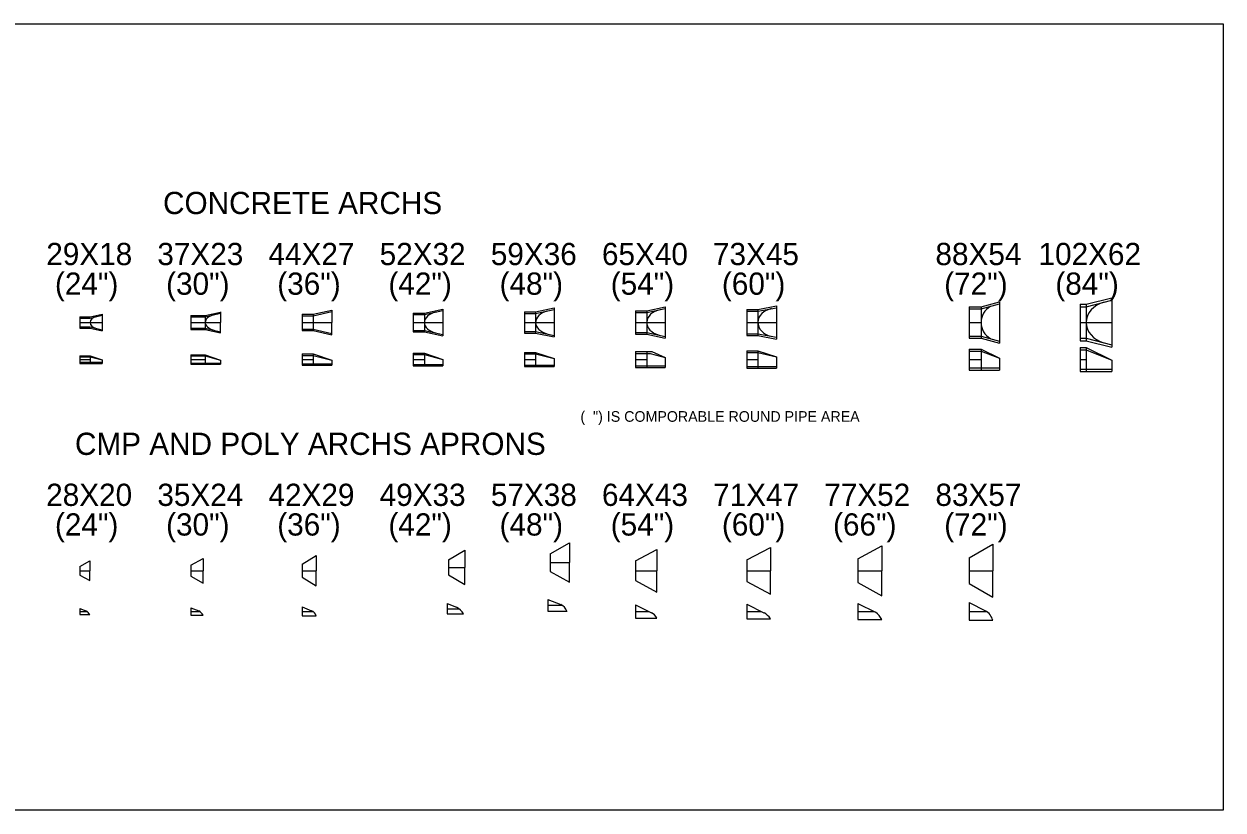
# Model space of a CAD drawing. Extents: x 14089015 to 14094575, y 8545767 to 8546666.
# Drawn here: x 14094251.7 to 14094575.3, y 8546454.2 to 8546666.4 of the extents above; entities that cross this region are included whole.
import ezdxf

# ---------------------------------------------------------------- set-up
doc = ezdxf.new("R2010")
doc.units = 0
doc.layers.add('CulvertExisting', color=7, linetype='Continuous')

msp = doc.modelspace()

# ---------------------------------------------------------------- linework, layer by layer
at = {"layer": 'CulvertExisting'}
for p, q in [((14094538.37, 8546590.73), (14094545.29, 8546592.48)), ((14094538.37, 8546590.06), (14094545.29, 8546591.81)), ((14094545.29, 8546592.48), (14094545.29, 8546579.15)), ((14094300.62, 8546587.69), (14094304.79, 8546588.64)), ((14094300.62, 8546587.36), (14094304.79, 8546588.31)), ((14094304.79, 8546588.65), (14094304.79, 8546585.81)), ((14094329.79, 8546588.02), (14094334.79, 8546589.17)), ((14094329.79, 8546587.65), (14094334.79, 8546588.81)), ((14094334.79, 8546589.17), (14094334.79, 8546585.81)), ((14094356.79, 8546588.36), (14094356.79, 8546583.27)), ((14094356.79, 8546588.36), (14094359.79, 8546588.36)), ((14094359.79, 8546588.36), (14094364.79, 8546589.44)), ((14094359.79, 8546587.98), (14094364.79, 8546589.06)), ((14094359.79, 8546588.36), (14094359.79, 8546583.27)), ((14094364.79, 8546589.44), (14094364.79, 8546582.19)), ((14094386.79, 8546588.69), (14094386.79, 8546582.94)), ((14094386.79, 8546588.69), (14094389.79, 8546588.69)), ((14094386.79, 8546588.27), (14094389.79, 8546588.27)), ((14094389.79, 8546588.69), (14094394.79, 8546589.73)), ((14094389.79, 8546588.27), (14094394.79, 8546589.31)), ((14094389.79, 8546588.69), (14094389.79, 8546582.94)), ((14094394.79, 8546589.73), (14094394.79, 8546581.9)), ((14094416.79, 8546588.98), (14094416.79, 8546582.65)), ((14094416.79, 8546588.98), (14094419.79, 8546588.98)), ((14094416.79, 8546588.52), (14094419.79, 8546588.52)), ((14094419.79, 8546588.98), (14094424.79, 8546590.02)), ((14094419.79, 8546588.52), (14094424.79, 8546589.56)), ((14094419.79, 8546588.98), (14094419.79, 8546582.65)), ((14094424.79, 8546590.02), (14094424.79, 8546581.61)), ((14094446.79, 8546589.36), (14094446.79, 8546582.27)), ((14094446.79, 8546589.36), (14094449.79, 8546589.36)), ((14094446.79, 8546588.86), (14094449.79, 8546588.86)), ((14094449.79, 8546589.36), (14094454.79, 8546590.31)), ((14094449.79, 8546588.86), (14094454.79, 8546589.81)), ((14094449.79, 8546589.36), (14094449.79, 8546582.27)), ((14094454.79, 8546590.31), (14094454.79, 8546581.31)), ((14094506.79, 8546590.06), (14094506.79, 8546581.56)), ((14094506.79, 8546590.06), (14094510.04, 8546590.06)), ((14094506.79, 8546589.48), (14094510.04, 8546589.48)), ((14094510.04, 8546590.06), (14094515.04, 8546591.4)), ((14094510.04, 8546589.48), (14094515.04, 8546590.81)), ((14094510.04, 8546590.06), (14094510.04, 8546581.56)), ((14094515.04, 8546591.4), (14094515.04, 8546580.23)), ((14094536.79, 8546590.73), (14094536.79, 8546580.9)), ((14094536.79, 8546590.73), (14094538.37, 8546590.73)), ((14094536.79, 8546590.06), (14094538.37, 8546590.06)), ((14094538.37, 8546590.73), (14094538.37, 8546580.9)), ((14094266.79, 8546587.31), (14094269.54, 8546587.31)), ((14094266.79, 8546587.31), (14094266.79, 8546584.32)), ((14094266.79, 8546587.02), (14094269.54, 8546587.02)), ((14094266.79, 8546585.81), (14094272.79, 8546585.81)), ((14094269.54, 8546587.31), (14094272.79, 8546588.1)), ((14094269.54, 8546587.02), (14094272.79, 8546587.81)), ((14094272.79, 8546588.1), (14094272.79, 8546583.52)), ((14094296.79, 8546587.69), (14094296.79, 8546583.94)), ((14094296.79, 8546587.69), (14094300.62, 8546587.69)), ((14094296.79, 8546587.36), (14094300.62, 8546587.36)), ((14094296.79, 8546585.81), (14094304.79, 8546585.81)), ((14094300.62, 8546587.69), (14094300.62, 8546583.94)), ((14094304.79, 8546582.98), (14094304.79, 8546585.81)), ((14094326.79, 8546588.02), (14094326.79, 8546583.61)), ((14094326.79, 8546588.02), (14094329.79, 8546588.02)), ((14094326.79, 8546587.65), (14094329.79, 8546587.65)), ((14094326.79, 8546585.81), (14094334.79, 8546585.81)), ((14094329.79, 8546588.02), (14094329.79, 8546583.61)), ((14094334.79, 8546582.46), (14094334.79, 8546585.81)), ((14094356.79, 8546587.98), (14094359.79, 8546587.98)), ((14094356.79, 8546585.81), (14094364.79, 8546585.81)), ((14094386.79, 8546585.81), (14094394.79, 8546585.81)), ((14094416.79, 8546585.81), (14094424.79, 8546585.81)), ((14094446.79, 8546585.81), (14094454.79, 8546585.81)), ((14094506.79, 8546585.81), (14094510.04, 8546585.81)), ((14094536.79, 8546585.81), (14094545.29, 8546585.81)), ((14094266.79, 8546584.61), (14094269.54, 8546584.61)), ((14094266.79, 8546584.32), (14094269.54, 8546584.32)), ((14094269.54, 8546584.61), (14094272.79, 8546583.81)), ((14094269.54, 8546584.32), (14094272.79, 8546583.52)), ((14094296.79, 8546584.27), (14094300.62, 8546584.27)), ((14094296.79, 8546583.94), (14094300.62, 8546583.94)), ((14094300.62, 8546584.27), (14094304.79, 8546583.31)), ((14094300.62, 8546583.94), (14094304.79, 8546582.98)), ((14094326.79, 8546583.98), (14094329.79, 8546583.98)), ((14094326.79, 8546583.61), (14094329.79, 8546583.61)), ((14094329.79, 8546583.98), (14094334.79, 8546582.81)), ((14094329.79, 8546583.61), (14094334.79, 8546582.46)), ((14094356.79, 8546583.65), (14094359.79, 8546583.65)), ((14094356.79, 8546583.27), (14094359.79, 8546583.27)), ((14094359.79, 8546583.65), (14094364.79, 8546582.56)), ((14094359.79, 8546583.27), (14094364.79, 8546582.19)), ((14094386.79, 8546583.36), (14094389.79, 8546583.36)), ((14094386.79, 8546582.94), (14094389.79, 8546582.94)), ((14094389.79, 8546583.36), (14094394.79, 8546582.31)), ((14094389.79, 8546582.94), (14094394.79, 8546581.9)), ((14094416.79, 8546583.11), (14094419.79, 8546583.11)), ((14094416.79, 8546582.65), (14094419.79, 8546582.65)), ((14094419.79, 8546583.11), (14094424.79, 8546582.06)), ((14094419.79, 8546582.65), (14094424.79, 8546581.61)), ((14094446.79, 8546582.77), (14094449.79, 8546582.77)), ((14094446.79, 8546582.27), (14094449.79, 8546582.27)), ((14094449.79, 8546582.77), (14094454.79, 8546581.81)), ((14094449.79, 8546582.27), (14094454.79, 8546581.31)), ((14094506.79, 8546582.15), (14094510.04, 8546582.15)), ((14094510.04, 8546582.15), (14094515.04, 8546580.81)), ((14094506.79, 8546581.56), (14094510.04, 8546581.56)), ((14094506.79, 8546578.65), (14094506.79, 8546572.98)), ((14094506.79, 8546578.65), (14094510.04, 8546578.65)), ((14094510.04, 8546581.56), (14094515.04, 8546580.23)), ((14094510.04, 8546578.65), (14094510.04, 8546572.98)), ((14094510.04, 8546578.65), (14094515.04, 8546576.15)), ((14094536.79, 8546581.56), (14094538.37, 8546581.56)), ((14094536.79, 8546580.9), (14094538.37, 8546580.9)), ((14094536.79, 8546579.06), (14094536.79, 8546572.56)), ((14094536.79, 8546579.06), (14094538.37, 8546579.06)), ((14094538.37, 8546581.56), (14094545.29, 8546579.81)), ((14094538.37, 8546580.9), (14094545.29, 8546579.15)), ((14094538.37, 8546579.06), (14094538.37, 8546572.56)), ((14094538.37, 8546579.06), (14094545.29, 8546575.61)), ((14094266.79, 8546576.85), (14094269.54, 8546576.85)), ((14094266.79, 8546576.85), (14094266.79, 8546574.77)), ((14094266.79, 8546576.56), (14094269.54, 8546576.56)), ((14094266.79, 8546575.81), (14094269.54, 8546575.81)), ((14094269.54, 8546576.85), (14094272.79, 8546575.77)), ((14094269.54, 8546576.85), (14094269.54, 8546574.77)), ((14094269.54, 8546576.56), (14094272.79, 8546575.77)), ((14094272.79, 8546575.77), (14094272.79, 8546574.77)), ((14094296.79, 8546577.1), (14094296.79, 8546574.53)), ((14094296.79, 8546577.1), (14094300.62, 8546577.1)), ((14094296.79, 8546576.77), (14094300.62, 8546576.77)), ((14094296.79, 8546575.81), (14094300.62, 8546575.81)), ((14094300.62, 8546577.1), (14094300.62, 8546574.53)), ((14094300.62, 8546577.1), (14094304.79, 8546575.66)), ((14094300.62, 8546576.77), (14094304.79, 8546575.66)), ((14094304.79, 8546575.66), (14094304.79, 8546574.53)), ((14094326.79, 8546577.31), (14094326.79, 8546574.31)), ((14094326.79, 8546577.31), (14094329.79, 8546577.31)), ((14094326.79, 8546576.94), (14094329.79, 8546576.94)), ((14094326.79, 8546575.81), (14094329.79, 8546575.81)), ((14094329.79, 8546577.31), (14094329.79, 8546574.31)), ((14094329.79, 8546577.31), (14094334.79, 8546575.62)), ((14094329.79, 8546576.94), (14094334.79, 8546575.62)), ((14094334.79, 8546575.62), (14094334.79, 8546574.31)), ((14094356.79, 8546577.52), (14094356.79, 8546574.11)), ((14094356.79, 8546577.52), (14094359.79, 8546577.52)), ((14094356.79, 8546577.15), (14094359.79, 8546577.15)), ((14094356.79, 8546575.81), (14094359.79, 8546575.81)), ((14094359.79, 8546577.52), (14094364.79, 8546575.8)), ((14094359.79, 8546577.15), (14094359.79, 8546574.11)), ((14094359.79, 8546577.15), (14094364.79, 8546575.8)), ((14094364.79, 8546575.8), (14094364.79, 8546574.11)), ((14094386.79, 8546577.73), (14094386.79, 8546573.9)), ((14094386.79, 8546577.73), (14094389.79, 8546577.73)), ((14094386.79, 8546577.31), (14094389.79, 8546577.31)), ((14094386.79, 8546575.81), (14094389.79, 8546575.81)), ((14094389.79, 8546577.73), (14094389.79, 8546573.9)), ((14094389.79, 8546577.73), (14094394.79, 8546576.06)), ((14094389.79, 8546577.31), (14094394.79, 8546576.06)), ((14094394.79, 8546576.06), (14094394.79, 8546573.9)), ((14094416.79, 8546577.94), (14094416.79, 8546573.69)), ((14094416.79, 8546577.94), (14094421.13, 8546577.94)), ((14094416.79, 8546577.48), (14094420.72, 8546577.48)), ((14094416.79, 8546575.81), (14094419.79, 8546575.81)), ((14094419.79, 8546577.94), (14094419.79, 8546573.69)), ((14094420.72, 8546577.48), (14094424.79, 8546576.36)), ((14094421.21, 8546577.94), (14094424.79, 8546576.36)), ((14094424.79, 8546576.36), (14094424.79, 8546573.69)), ((14094446.79, 8546578.19), (14094446.79, 8546573.44)), ((14094446.79, 8546578.19), (14094449.79, 8546578.19)), ((14094446.79, 8546577.69), (14094449.79, 8546577.69)), ((14094446.79, 8546575.81), (14094449.79, 8546575.81)), ((14094449.79, 8546578.19), (14094449.79, 8546573.44)), ((14094449.79, 8546578.19), (14094454.79, 8546576.52)), ((14094449.79, 8546577.69), (14094454.79, 8546576.52)), ((14094454.79, 8546576.52), (14094454.79, 8546573.44)), ((14094506.79, 8546578.06), (14094510.04, 8546578.06)), ((14094506.79, 8546575.81), (14094510.04, 8546575.81)), ((14094510.04, 8546578.06), (14094515.04, 8546576.15)), ((14094515.04, 8546576.15), (14094515.04, 8546572.98)), ((14094536.79, 8546578.4), (14094538.37, 8546578.4)), ((14094536.79, 8546575.81), (14094538.37, 8546575.81)), ((14094538.37, 8546578.4), (14094545.29, 8546575.61)), ((14094545.29, 8546575.61), (14094545.29, 8546572.56)), ((14094266.79, 8546575.06), (14094272.79, 8546575.06)), ((14094266.79, 8546574.77), (14094272.79, 8546574.77)), ((14094296.79, 8546574.86), (14094304.79, 8546574.86)), ((14094296.79, 8546574.53), (14094304.79, 8546574.53)), ((14094326.79, 8546574.69), (14094334.79, 8546574.69)), ((14094326.79, 8546574.31), (14094334.79, 8546574.31)), ((14094356.79, 8546574.48), (14094359.79, 8546574.48)), ((14094356.79, 8546574.11), (14094359.79, 8546574.11)), ((14094359.79, 8546574.48), (14094364.79, 8546574.48)), ((14094359.79, 8546574.11), (14094364.79, 8546574.11)), ((14094386.79, 8546574.31), (14094389.79, 8546574.31)), ((14094386.79, 8546573.9), (14094389.79, 8546573.9)), ((14094389.79, 8546574.31), (14094394.79, 8546574.31)), ((14094389.79, 8546573.9), (14094394.79, 8546573.9)), ((14094416.79, 8546574.15), (14094420.8, 8546574.15)), ((14094416.79, 8546573.69), (14094420.96, 8546573.69)), ((14094420.8, 8546574.15), (14094424.79, 8546574.15)), ((14094420.96, 8546573.69), (14094424.79, 8546573.69)), ((14094446.79, 8546573.94), (14094449.79, 8546573.94)), ((14094446.79, 8546573.44), (14094449.79, 8546573.44)), ((14094449.79, 8546573.94), (14094454.79, 8546573.94)), ((14094449.79, 8546573.44), (14094454.79, 8546573.44)), ((14094506.79, 8546573.56), (14094510.04, 8546573.56)), ((14094506.79, 8546572.98), (14094510.04, 8546572.98)), ((14094510.04, 8546573.56), (14094515.04, 8546573.56)), ((14094510.04, 8546572.98), (14094515.04, 8546572.98)), ((14094536.79, 8546573.23), (14094538.37, 8546573.23)), ((14094536.79, 8546572.56), (14094538.37, 8546572.56)), ((14094538.37, 8546573.23), (14094545.29, 8546573.23)), ((14094538.37, 8546572.56), (14094545.29, 8546572.56)), ((14094366.27, 8546521.74), (14094370.69, 8546524.32)), ((14094370.69, 8546524.32), (14094370.69, 8546519.7)), ((14094393.77, 8546523.39), (14094398.93, 8546526.3)), ((14094398.93, 8546526.3), (14094398.93, 8546521.01)), ((14094416.79, 8546521.48), (14094422.54, 8546524.56)), ((14094422.54, 8546524.56), (14094422.54, 8546518.81)), ((14094446.79, 8546521.77), (14094453.21, 8546525.11)), ((14094453.21, 8546525.11), (14094453.21, 8546518.81)), ((14094476.79, 8546522.02), (14094483.21, 8546525.56)), ((14094483.21, 8546525.56), (14094483.21, 8546518.81)), ((14094506.79, 8546522.27), (14094513.21, 8546525.94)), ((14094513.21, 8546525.94), (14094513.21, 8546518.81)), ((14094266.79, 8546519.98), (14094269.46, 8546521.48)), ((14094269.46, 8546521.48), (14094269.46, 8546518.81)), ((14094296.79, 8546520.27), (14094300.04, 8546522.15)), ((14094300.04, 8546522.15), (14094300.04, 8546518.81)), ((14094326.79, 8546520.56), (14094330.62, 8546522.94)), ((14094326.79, 8546520.56), (14094326.79, 8546517.06)), ((14094330.62, 8546522.94), (14094330.62, 8546518.81)), ((14094366.27, 8546521.74), (14094366.27, 8546517.66)), ((14094393.77, 8546523.39), (14094393.77, 8546518.64)), ((14094393.77, 8546521.01), (14094398.93, 8546521.01)), ((14094398.93, 8546515.72), (14094398.93, 8546521.01)), ((14094416.79, 8546521.48), (14094416.79, 8546516.15)), ((14094446.79, 8546521.77), (14094446.79, 8546515.86)), ((14094476.79, 8546522.02), (14094476.79, 8546515.61)), ((14094506.79, 8546522.27), (14094506.79, 8546515.36)), ((14094266.79, 8546519.98), (14094266.79, 8546517.65)), ((14094266.79, 8546518.81), (14094269.46, 8546518.81)), ((14094266.79, 8546517.65), (14094269.46, 8546516.15)), ((14094269.46, 8546516.15), (14094269.46, 8546518.81)), ((14094296.79, 8546520.27), (14094296.79, 8546517.36)), ((14094296.79, 8546518.81), (14094300.04, 8546518.81)), ((14094296.79, 8546517.36), (14094300.04, 8546515.48)), ((14094300.04, 8546515.48), (14094300.04, 8546518.81)), ((14094326.79, 8546518.81), (14094330.62, 8546518.81)), ((14094326.79, 8546517.06), (14094330.62, 8546514.69)), ((14094330.62, 8546514.69), (14094330.62, 8546518.81)), ((14094366.27, 8546519.7), (14094370.69, 8546519.7)), ((14094366.27, 8546517.66), (14094370.69, 8546515.07)), ((14094370.69, 8546515.07), (14094370.69, 8546519.7)), ((14094393.77, 8546518.64), (14094398.93, 8546515.72)), ((14094416.79, 8546518.81), (14094422.54, 8546518.81)), ((14094422.54, 8546513.06), (14094422.54, 8546518.81)), ((14094446.79, 8546518.81), (14094453.21, 8546518.81)), ((14094453.21, 8546512.52), (14094453.21, 8546518.81)), ((14094476.79, 8546518.81), (14094483.21, 8546518.81)), ((14094483.21, 8546512.06), (14094483.21, 8546518.81)), ((14094506.79, 8546518.81), (14094513.21, 8546518.81)), ((14094513.21, 8546511.69), (14094513.21, 8546518.81)), ((14094416.79, 8546516.15), (14094422.54, 8546513.06)), ((14094446.79, 8546515.86), (14094453.21, 8546512.52)), ((14094476.79, 8546515.61), (14094483.21, 8546512.06)), ((14094506.79, 8546515.36), (14094513.21, 8546511.69)), ((14094393.11, 8546511.06), (14094393.11, 8546507.89)), ((14094393.11, 8546511.06), (14094396.58, 8546509.67)), ((14094266.79, 8546508.65), (14094266.79, 8546506.98)), ((14094266.79, 8546508.65), (14094268.41, 8546508)), ((14094266.79, 8546507.81), (14094268.72, 8546507.81)), ((14094296.79, 8546508.81), (14094296.79, 8546506.81)), ((14094296.79, 8546508.81), (14094298.9, 8546507.97)), ((14094296.79, 8546507.81), (14094299.16, 8546507.81)), ((14094326.79, 8546509.02), (14094326.79, 8546506.61)), ((14094326.79, 8546509.02), (14094329.29, 8546508.02)), ((14094326.79, 8546507.81), (14094329.69, 8546507.81)), ((14094365.94, 8546509.93), (14094365.94, 8546507.18)), ((14094365.94, 8546509.93), (14094368.44, 8546508.93)), ((14094365.94, 8546508.56), (14094369.07, 8546508.56)), ((14094393.11, 8546509.47), (14094396.98, 8546509.47)), ((14094393.11, 8546507.89), (14094398.28, 8546507.89)), ((14094416.79, 8546509.61), (14094416.79, 8546506.02)), ((14094416.79, 8546509.61), (14094421.07, 8546507.47)), ((14094416.79, 8546507.81), (14094420.37, 8546507.81)), ((14094446.79, 8546509.77), (14094446.79, 8546505.86)), ((14094446.79, 8546509.77), (14094451.44, 8546507.44)), ((14094446.79, 8546507.81), (14094450.71, 8546507.81)), ((14094476.79, 8546509.98), (14094476.79, 8546505.65)), ((14094476.79, 8546509.98), (14094481.55, 8546507.6)), ((14094476.79, 8546507.81), (14094481.12, 8546507.81)), ((14094506.79, 8546510.19), (14094506.79, 8546505.44)), ((14094506.79, 8546510.19), (14094511.18, 8546507.99)), ((14094506.79, 8546507.81), (14094511.48, 8546507.81)), ((14094266.79, 8546506.98), (14094269.46, 8546506.98)), ((14094296.79, 8546506.81), (14094300.04, 8546506.81)), ((14094326.79, 8546506.61), (14094330.62, 8546506.61)), ((14094365.94, 8546507.18), (14094370.36, 8546507.18)), ((14094416.79, 8546506.02), (14094422.54, 8546506.02)), ((14094446.79, 8546505.86), (14094453.21, 8546505.86)), ((14094476.79, 8546505.65), (14094483.21, 8546505.65)), ((14094506.79, 8546505.44), (14094513.21, 8546505.44))]:
    msp.add_line(p, q, dxfattribs=at)
msp.add_lwpolyline([(14093936.03, 8546666.39), (14094575.33, 8546666.39), (14094575.33, 8546454.22), (14093936.03, 8546454.22)], close=True, dxfattribs=at)
for centre, radius, start, end in [((14094515.04, 8546585.81), 5, 119.8557, 240.1443), ((14094267.37, 8546505.88), 2.36, 27.7999, 63.7435), ((14094297.68, 8546505.63), 2.64, 26.7139, 62.4576), ((14094328.41, 8546505.86), 2.33, 18.5594, 67.8529), ((14094366.32, 8546504.68), 4.76, 31.7729, 63.4421), ((14094395.46, 8546506.9), 2.98, 19.3212, 67.9747), ((14094419.78, 8546504.68), 3.07, 25.9019, 65.1898), ((14094449.14, 8546503.12), 4.9, 33.9679, 61.9791), ((14094479.41, 8546504.11), 4.09, 22.0609, 58.4869), ((14094509.16, 8546504.31), 4.19, 15.5448, 61.2381)]:
    msp.add_arc(centre, radius, start, end, dxfattribs=at)
for centre, major_axis, ratio, start_param, end_param in [((14094364.79, 8546585.81), (5, 0), 0.612657, 1.972753, 4.315207), ((14094394.79, 8546585.81), (5, 0), 0.663215, 1.931438, 4.362765), ((14094424.79, 8546585.81), (5, 0), 0.720353, 1.84961, 4.37216), ((14094454.79, 8546585.81), (5, 0), 0.775843, 1.831288, 4.416311), ((14094545.29, 8546585.81), (6.92, 0), 0.825892, 1.876172, 4.402684), ((14094272.79, 8546585.81), (3.25, 0), 0.56441, 2.039314, 4.244804), ((14094304.79, 8546585.81), (4.17, 0), 0.553152, 2.002656, 4.256657)]:
    msp.add_ellipse(centre, major_axis=major_axis, ratio=ratio, start_param=start_param, end_param=end_param, dxfattribs=at)

# ---------------------------------------------------------------- texts
for s, height, p in [('CONCRETE ARCHS', 6, (14094289.25, 8546615.07)), ('29X18', 6, (14094257.73, 8546601.3)), ('37X23', 6, (14094287.71, 8546601.3)), ('44X27', 6, (14094317.71, 8546601.3)), ('52X32', 6, (14094347.71, 8546601.3)), ('59X36', 6, (14094377.71, 8546601.3)), ('65X40', 6, (14094407.71, 8546601.3)), ('73X45', 6, (14094437.67, 8546601.3)), ('88X54', 6, (14094497.71, 8546601.3)), ('102X62', 6, (14094525.53, 8546601.3)), ('(24")', 6, (14094260.08, 8546593.3)), ('(30")', 6, (14094290.08, 8546593.3)), ('(36")', 6, (14094320.08, 8546593.3)), ('(42")', 6, (14094350.08, 8546593.3)), ('(48")', 6, (14094380.08, 8546593.3)), ('(54")', 6, (14094410.08, 8546593.3)), ('(60")', 6, (14094440.08, 8546593.3)), ('(72")', 6, (14094500.08, 8546593.3)), ('(84")', 6, (14094530.08, 8546593.3)), ('(  ") IS COMPORABLE ROUND PIPE AREA', 2.8698, (14094401.9, 8546559.01)), ('CMP AND POLY ARCHS APRONS', 6, (14094265.48, 8546550.07)), ('28X20', 6, (14094257.71, 8546536.3)), ('35X24', 6, (14094287.71, 8546536.3)), ('42X29', 6, (14094317.71, 8546536.3)), ('49X33', 6, (14094347.71, 8546536.3)), ('57X38', 6, (14094377.73, 8546536.3)), ('64X43', 6, (14094407.71, 8546536.3)), ('71X47', 6, (14094437.71, 8546536.3)), ('77X52', 6, (14094467.71, 8546536.3)), ('83X57', 6, (14094497.71, 8546536.3)), ('(24")', 6, (14094260.08, 8546528.3)), ('(30")', 6, (14094290.08, 8546528.3)), ('(36")', 6, (14094320.08, 8546528.3)), ('(42")', 6, (14094350.08, 8546528.3)), ('(48")', 6, (14094380.08, 8546528.3)), ('(54")', 6, (14094410.08, 8546528.3)), ('(60")', 6, (14094440.08, 8546528.3)), ('(66")', 6, (14094470.08, 8546528.3)), ('(72")', 6, (14094500.08, 8546528.3))]:
    msp.add_text(s, height=height, dxfattribs=at).set_placement(p)

doc.saveas('drawing.dxf')
